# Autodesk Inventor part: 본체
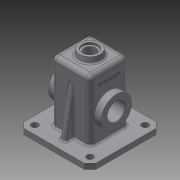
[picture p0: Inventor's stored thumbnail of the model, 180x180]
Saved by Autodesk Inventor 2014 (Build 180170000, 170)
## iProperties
Created: 2016-02
Part Number: 본체
Material: Generic
Document SubType Name: Modeling
Designer: user
Density: 1 g/cm^3
Appearance: Default
Mass: 344.211 g
Surface Area: 1043.49 cm^2
Volume: 344.211 cm^3
Author: user
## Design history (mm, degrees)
sketch "Sketch1"
  geometry: L1 (-35, 35)-(35, 35); L2 (35, 35)-(35, -35); L3 (35, -35)-(-35, -35); L4 (-35, -35)-(-35, 35); 3 further points
  constraints: 8 end point, 2 midpoint, 2 parallel, 1 horizontal, 1 horizontal alignment, 1 perpendicular, 1 vertical alignment
  dimensions: "d0" = 70 distance of L2.end L3.end; "d1" = 70 distance of L3.end L1.start
extrude "Extrusion1" new body sketch "Sketch1" distance "d2" = 120; taper "d3" = 0 deg
sketch "Sketch2"
  geometry: L1 (70, 0)-(0, 0) reference; L2 (0, 120)-(70, 120) reference; C1 r 27.5 at (35, 55); 2 further points
  constraints: 1 centre point, 1 midpoint, 1 vertical alignment
  dimensions: "d4" = 55 diameter of C1; "d5" = 55 distance from line of L1 C1.centre
shell "Shell1" dims "d6" = 5
extrude "Extrusion2" join sketch "Sketch2" distance "d7" = 13; taper "d8" = 0 deg
sketch "Sketch3"
  geometry: C1 r 27.5 at (0, 0) reference; C2 r 16 at (0, 0); 1 further point
  constraints: 1 centre point, 1 concentric
  dimensions: "d9" = 32 diameter of C2
extrude "Extrusion3" cut sketch "Sketch3" stored distance "d10" = 13; taper "d11" = 0 deg
sketch "Sketch4"
  geometry: C1 r 16 at (35, 55) reference; C2 r 27.5 at (35, 55); 1 further point
  constraints: 1 centre point, 1 concentric
  dimensions: "d12" = 55 diameter of C2
extrude "Extrusion4" join sketch "Sketch4" distance "d13" = 13; taper "d14" = 0 deg
fillet "Fillet1" dims "d15" = 8
fillet "Fillet2" dims "d16" = 0.5
sketch "Sketch5"
  geometry: C1 r 16 at (0, 0) reference; 2 further points
  constraints: 1 vertical alignment
  dimensions: "d17" = 22.5 distance of C1.centre point (0, 22.5)
hole "Hole1" sketch "Sketch5" at (0, 22.5) diameter "d18" = 3.242; stored, may be unused: countersink angle "d22" = 90 deg, drill point angle "d24" = 118 deg; dims "d19" = 8, "d20" = 4, "d21" = 2, "d23" = 10
pattern_circular "Circular Pattern1" dims angle "d26" = 360 deg
sketch "Sketch6"
  geometry: C1 r 16 at (0, 0) reference; 2 further points
  constraints: 1 vertical alignment
  dimensions: "d28" = 22.5 distance of C1.centre point (0, 22.5)
hole "Hole2" sketch "Sketch6" at (0, 22.5) diameter "d29" = 3.242; stored, may be unused: countersink angle "d33" = 90 deg, drill point angle "d35" = 118 deg; dims "d30" = 8, "d31" = 4, "d32" = 2, "d34" = 10
pattern_circular "Circular Pattern2" dims angle "d37" = 360 deg
sketch "Sketch7"
  geometry: L1 (-27, -35)-(27, -35) reference; L2 (35, -27)-(35, 27) reference; L3 (27, 35)-(-27, 35) reference; L4 (-35, 27)-(-35, -27) reference; L5 (-65, 65)-(65, 65); L6 (65, 65)-(65, -65); L7 (65, -65)-(-65, -65); L8 (-65, -65)-(-65, 65); A1 r 8 centre (-27, -27) between (-35, -27) and (-27, -35) reference; A2 r 8 centre (27, -27) between (27, -35) and (35, -27) reference; A3 r 8 centre (27, 27) between (35, 27) and (27, 35) reference; A4 r 8 centre (-27, 27) between (-27, 35) and (-35, 27) reference; 3 further points
  constraints: 8 end point, 2 midpoint, 2 parallel, 1 horizontal, 1 horizontal alignment, 1 perpendicular, 1 vertical alignment
  dimensions: "d39" = 130 distance of L5.start L5.end; "d40" = 130 distance of L5.end L6.end
extrude "Extrusion5" join sketch "Sketch7" distance "d41" = 10; taper "d42" = 0 deg
fillet "Fillet3" dims "d43" = 8
chamfer "Chamfer1" distance "d44" = 10; stored, may be unused: second distance "d45" = 2, angle "d46" = 45 deg
sketch "Sketch8"
  geometry: C1 r 20 at (0, 0); 1 further point
  constraints: 1 centre point, 1 coincident
  dimensions: "d47" = 40 diameter of C1
extrude "Extrusion6" join sketch "Sketch8" distance "d48" = 10; taper "d49" = 0 deg
sketch "Sketch9"
  geometry: L1 (120, 27)-(120, 20) reference; L2 (120, 20)-(130, 20) reference; L3 (130, 20)-(130, -20) reference; L4 (130, -20)-(120, -20) reference; L5 (120, -20)-(120, -27) reference; L6 (112, -35)-(10, -35) reference; L7 (10, -35)-(10, -65) reference; L8 (10, -65)-(0, -65) reference; L9 (0, -65)-(0, -30) reference; L10 (0, -30)-(115, -30) reference; L11 (115, -30)-(115, 30) reference; L12 (115, 30)-(0, 30) reference; L13 (0, 30)-(0, 65) reference; L14 (0, 65)-(10, 65) reference; L15 (10, 65)-(10, 35) reference; L16 (10, 35)-(112, 35) reference; L17 (120, -20)-(130, -18.237); L18 (-26, 0)-(156, 0) reference; A1 r 8 centre (112, 27) between (120, 27) and (112, 35) reference; A2 r 8 centre (112, -27) between (112, -35) and (120, -27) reference; 1 further point
  constraints: 2 end point, 1 point on line
  dimensions: "d51" = 10 deg angle of L6 L17
revolve "Revolution1" sketch "Sketch9" stored, may be unused: angle "d52" = 90 deg
sketch "Sketch10"
  geometry: C1 r 18.237 at (0, 0) reference; C2 r 14 at (0, 0)
  constraints: 1 centre point, 1 concentric
  dimensions: "d53" = 28 diameter of C2
extrude "Extrusion7" cut sketch "Sketch10" distance "d54" = 4; taper "d55" = 0 deg
sketch "Sketch11"
  geometry: C1 r 10.5 at (0, 0); C2 r 14 at (0, 0) reference
  constraints: 1 centre point, 1 concentric
  dimensions: "d56" = 21 diameter of C1
extrude "Extrusion8" cut sketch "Sketch11" stored distance "d57" = 4; taper "d58" = 0 deg
fillet "Fillet4" dims "d59" = 3
chamfer "Chamfer2" distance "d60" = 1; stored, may be unused: second distance "d61" = 2, angle "d62" = 45 deg
sketch "Sketch12"
  geometry: C1 r 16 at (-30, 55) reference; C2 r 27.5 at (-30, 55); 1 further point
  constraints: 1 centre point, 1 concentric
  dimensions: "d63" = 55 diameter of C2
extrude "Extrusion9" join sketch "Sketch12" distance "d64" = 7; taper "d65" = 0 deg
sketch "Sketch13"
  geometry: C1 r 16 at (-30, 55) reference; C2 r 27.5 at (-30, 55); 1 further point
  constraints: 1 centre point, 1 concentric
  dimensions: "d66" = 55 diameter of C2
extrude "Extrusion10" join sketch "Sketch13" distance "d67" = 7; taper "d68" = 0 deg
sketch "Sketch14"
  geometry: L1 (-37.026, 77.5)-(-38, 79.121) reference; L2 (-38, 79.121)-(-48, 79.121) reference; L3 (-48, 79.121)-(-48, 82.5) reference; L4 (-48, 82.5)-(-35.5, 82.5) reference; L5 (-35, 83)-(-35, 112) reference; L6 (-27, 120)-(-22.517, 120) reference; L7 (-19.563, 122.479)-(-18.237, 130) reference; L8 (-18.237, 130)-(-14, 130) reference; L9 (-14, 130)-(-14, 126) reference; L10 (-14, 126)-(-10.5, 126) reference; L11 (-10.5, 126)-(-10.5, 115) reference; L12 (-10.5, 115)-(-30, 115) reference; L13 (-30, 115)-(-30, 82.5) reference; L14 (-30, 82.5)-(-23, 82.5) reference; L15 (-23, 82.5)-(-23, 71) reference; L16 (-23, 71)-(-47, 71) reference; L17 (-47, 71)-(-48, 72) reference; L18 (-48, 72)-(-48, 75.879) reference; L19 (-48, 75.879)-(-38, 75.879) reference; L20 (-38, 75.879)-(-37.026, 77.5) reference; L21 (37.026, 32.5)-(38, 30.879) reference; L22 (38, 30.879)-(48, 30.879) reference; L23 (48, 30.879)-(48, 27.5) reference; L24 (48, 27.5)-(35.5, 27.5) reference; L25 (35, 27)-(35, 10) reference; L26 (35, 10)-(65, 10) reference; L27 (65, 10)-(65, 0) reference; L28 (65, 0)-(30, 0) reference; L29 (30, 0)-(30, 27.5) reference; L30 (30, 27.5)-(23, 27.5) reference; L31 (23, 27.5)-(23, 39) reference; L32 (23, 39)-(47, 39) reference; L33 (47, 39)-(48, 38) reference; L34 (48, 38)-(48, 34.121) reference; L35 (48, 34.121)-(38, 34.121) reference; L36 (38, 34.121)-(37.026, 32.5) reference; L37 (-35.5, 27.5)-(-48, 27.5) reference; L38 (-48, 27.5)-(-48, 30.879) reference; L39 (-48, 30.879)-(-38, 30.879) reference; L40 (-38, 30.879)-(-37.026, 32.5) reference; L41 (-37.026, 32.5)-(-38, 34.121) reference; L42 (-38, 34.121)-(-48, 34.121) reference; L43 (-48, 34.121)-(-48, 38) reference; L44 (-48, 38)-(-47, 39) reference; L45 (-47, 39)-(-23, 39) reference; L46 (-23, 39)-(-23, 27.5) reference; L47 (-23, 27.5)-(-30, 27.5) reference; L48 (-30, 27.5)-(-30, 0) reference; L49 (-30, 0)-(-65, 0) reference; L50 (-65, 0)-(-65, 10) reference; L51 (-65, 10)-(-35, 10) reference; L52 (-35, 10)-(-35, 27) reference; L53 (35.5, 82.5)-(48, 82.5) reference; L54 (48, 82.5)-(48, 79.121) reference; L55 (48, 79.121)-(38, 79.121) reference; L56 (38, 79.121)-(37.026, 77.5) reference; L57 (37.026, 77.5)-(38, 75.879) reference; L58 (38, 75.879)-(48, 75.879) reference; L59 (48, 75.879)-(48, 72) reference; L60 (48, 72)-(47, 71) reference; L61 (47, 71)-(23, 71) reference; L62 (23, 71)-(23, 82.5) reference; L63 (23, 82.5)-(30, 82.5) reference; L64 (30, 82.5)-(30, 115) reference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; A1 r 0.5 centre (-35.5, 83) between (-35.5, 82.5) and (-35, 83) reference; A2 r 8 centre (-27, 112) between (-27, 120) and (-35, 112) reference; A3 r 3 centre (-22.517, 123) between (-22.517, 120) and (-19.563, 122.479) reference; A4 r 0.5 centre (35.5, 27) between (35.5, 27.5) and (35, 27) reference; A5 r 0.5 centre (-35.5, 27) between (-35, 27) and (-35.5, 27.5) reference; A6 r 0.5 centre (35.5, 83) between (35, 83) and (35.5, 82.5) reference; A7 r 3 centre (22.517, 123) between (19.563, 122.479) and (22.517, 120) reference; A8 r 8 centre (27, 112) between (35, 112) and (27, 120) reference; A9 r 0.5 centre (-35.5, 83) between (-35.5, 82.5) and (-35, 83) reference; A10 r 8 centre (-27, 112) between (-27, 120) and (-35, 112) reference; A11 r 3 centre (-22.517, 123) between (-22.517, 120) and (-19.563, 122.479) reference; A12 r 0.5 centre (35.5, 27) between (35.5, 27.5) and (35, 27) reference; A13 r 0.5 centre (-35.5, 27) between (-35, 27) and (-35.5, 27.5) reference; A14 r 0.5 centre (35.5, 83) between (35, 83) and (35.5, 82.5) reference; A15 r 3 centre (22.517, 123) between (19.563, 122.479) and (22.517, 120) reference; A16 r 8 centre (27, 112) between (35, 112) and (27, 120) reference; 1 further point
  constraints: 6 end point, 2 point on line, 1 midpoint, 1 perpendicular
  dimensions: "d69" = 135 deg angle of L48 L73; "d70" = 135 deg angle of L29 L74
  node "Project Cut Edges2"
  node "Project Cut Edges3"
revolve "Revolution2" stored, may be unused: angle "d71" = 90 deg
fillet "Fillet5" dims "d72" = 0.5
sketch "Sketch15"
  geometry: L1 (10, -65)-(0, -65) reference; L2 (0, -65)-(0, -30) reference; L3 (0, -30)-(115, -30) reference; L4 (115, -30)-(115, -10.5) reference; L5 (115, -10.5)-(126, -10.5) reference; L6 (126, -10.5)-(126, -14) reference; L7 (126, -14)-(130, -14) reference; L8 (130, -14)-(130, -18.237) reference; L9 (130, -18.237)-(122.479, -19.563) reference; L10 (120, -22.517)-(120, -27) reference; L11 (112, -35)-(10, -35) reference; L12 (10, -35)-(10, -65) reference; L13 (10, 65)-(10, 35) reference; L14 (10, 35)-(112, 35) reference; L15 (120, 27)-(120, 22.517) reference; L16 (122.479, 19.563)-(130, 18.237) reference; L17 (130, 18.237)-(130, 14) reference; L18 (130, 14)-(126, 14) reference; L19 (126, 14)-(126, 10.5) reference; L20 (126, 10.5)-(115, 10.5) reference; L21 (115, 10.5)-(115, 30) reference; L22 (115, 30)-(0, 30) reference; L23 (0, 30)-(0, 65) reference; L24 (0, 65)-(10, 65) reference; L25 (10, -50)-(95.069, -35); L26 (10, 50)-(95.069, 35); A1 r 3 centre (123, -22.517) between (122.479, -19.563) and (120, -22.517) reference; A2 r 8 centre (112, -27) between (112, -35) and (120, -27) reference; A3 r 8 centre (112, 27) between (120, 27) and (112, 35) reference; A4 r 3 centre (123, 22.517) between (120, 22.517) and (122.479, 19.563) reference; 1 further point
  constraints: 4 end point, 2 midpoint, 2 point on line
  dimensions: "d73" = 15 distance from line of L1 L25.start; "d74" = 10 deg angle of L1 L25; "d75" = 15 distance from line of L24 L26.start; "d76" = 10 deg angle of L24 L26
  node "Project Cut Edges4"
feature "Rib1" dims "d77" = 1, "d78" = 10, "d79" = 0, "d80" = 0, "d81" = 1, "d82" = 1
feature "Rib2" dims "d83" = 1, "d84" = 10, "d85" = 0, "d86" = 0, "d87" = 1, "d88" = 1
fillet "Fillet6" dims "d89" = 3
fillet "Fillet7" dims "d90" = 3
fillet "Fillet8" dims "d91" = 3
sketch "Sketch16"
  geometry: L1 (65, -55)-(65, 55) reference; L2 (55, 65)-(-55, 65) reference; C1 r 6 at (50, 50); C2 r 6 at (-50, 50); C3 r 6 at (50, -50); C4 r 6 at (-50, -50); 1 further point
  constraints: 4 centre point, 1 horizontal, 1 vertical, 6 other
  dimensions: "d92" = 12 diameter of C1; "d93" = 15 distance from line of C1.centre L1; "d94" = 15 distance from line of L2 C1.centre; "d97" = 100 distance of C1.centre C2.centre; "d100" = 100 distance of C1.centre C3.centre
extrude "Extrusion11" cut sketch "Sketch16" stored distance "d103" = 7; taper "d104" = 0 deg
sketch "Sketch17"
  geometry: L1 (35, -42)-(35, 57) reference; L2 (18.237, 75)-(-18.237, 75) reference; 2 further points
  constraints: 1 other
  dimensions: "d105" = 35 distance from line of L1 point (0, 45); "d106" = 30 distance from line of L2 point (0, 45)
emboss "Emboss1" sketch "Sketch17" dims "d107" = 0.5, "d108" = 0
fillet "Fillet9" dims "d109" = 3
fillet "Fillet10" dims "d110" = 3
body "Solid1"
node "Project Cut Edges1"
